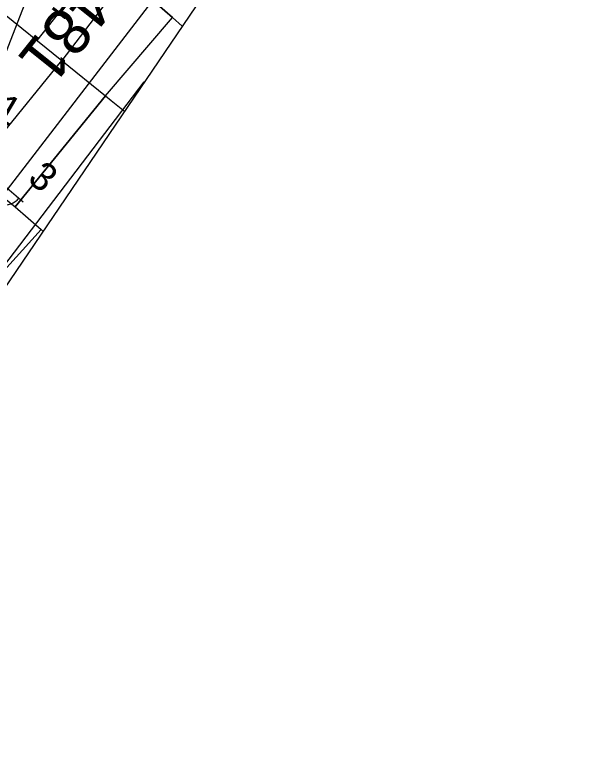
# Model space of a CAD drawing. Extents: x -621145 to -620110, y -1122807 to -1121971.
# Drawn here: x -620223.71 to -620192.94, y -1122754.28 to -1122715.36 of the extents above; entities that cross this region are included whole.
import ezdxf

# ---------------------------------------------------------------- set-up
doc = ezdxf.new("R2010")
doc.units = 0
for name, color, linetype in [('POPIS KABELOVÉ TRASY', 7, 'Continuous'), ('RÁMY', 7, 'Continuous'), ('SON-kanalizace', 7, 'Continuous'), ('Vrstva 25', 7, 'Continuous'), ('Vrstva 3', 7, 'Continuous'), ('Vrstva 53', 7, 'Continuous'), ('Vrstva 55', 7, 'Continuous'), ('Vrstva 56', 7, 'Continuous'), ('Vrstva 57', 7, 'Continuous'), ('Vrstva 6', 7, 'Continuous')]:
    doc.layers.add(name, color=color, linetype=linetype)

msp = doc.modelspace()

# ---------------------------------------------------------------- linework, layer by layer
at = {"layer": 'POPIS KABELOVÉ TRASY'}
msp.add_lwpolyline([(-620228.339, -1122728.069), (-620218.049, -1122701.604), (-620224.371, -1122697.311)], dxfattribs=at)
at = {"layer": 'RÁMY'}
for points in [[(-621061.558, -1122093.918), (-620192.937, -1122683.831), (-620276.367, -1122806.679), (-621144.989, -1122216.766)], [(-620887.834, -1122211.901), (-620192.937, -1122683.831), (-620276.367, -1122806.679), (-620971.264, -1122334.748)]]:
    msp.add_lwpolyline(points, close=True, dxfattribs=at)
at = {"layer": 'SON-kanalizace'}
msp.add_line((-620218.226, -1122711.312), (-620222.528, -1122716.741), dxfattribs=at)
msp.add_lwpolyline([(-620225.128, -1122704.565), (-620219.234, -1122709.235), (-620216.418, -1122711.556), (-620221.19, -1122717.82)], dxfattribs=at)
at = {"layer": 'Vrstva 25'}
msp.add_line((-620225.24, -1122723.667), (-620223.256, -1122725.347), dxfattribs=at)
msp.add_arc((-620224.256, -1122724.517), 1, 139.0457, 320.4509, dxfattribs=at)
at = {"layer": 'Vrstva 3'}
msp.add_line((-620230.199, -1122732.623), (-620210.91, -1122707.563), dxfattribs=at)
at = {"layer": 'Vrstva 53'}
for p, q in [((-620226.24, -1122705.93), (-620215.29, -1122715.52)), ((-620228.95, -1122711.56), (-620221.19, -1122717.82)), ((-620218.86, -1122719.7), (-620215.29, -1122715.52)), ((-620221.19, -1122717.82), (-620218.86, -1122719.7)), ((-620218.86, -1122719.7), (-620223.68, -1122725.62)), ((-620226.02, -1122723.74), (-620223.68, -1122725.62)), ((-620223.68, -1122725.62), (-620222.3, -1122726.83)), ((-620222.3, -1122726.83), (-620225.04, -1122729.85))]:
    msp.add_line(p, q, dxfattribs=at)
at = {"layer": 'Vrstva 55'}
for p, q in [((-620215.29, -1122715.52), (-620226.24, -1122705.93)), ((-620228.95, -1122711.56), (-620221.19, -1122717.82)), ((-620218.86, -1122719.7), (-620215.29, -1122715.52)), ((-620214.768, -1122715.977), (-620215.29, -1122715.52)), ((-620221.19, -1122717.82), (-620218.86, -1122719.7)), ((-620223.68, -1122725.62), (-620218.86, -1122719.7)), ((-620218.86, -1122719.7), (-620218.55, -1122719.95)), ((-620218.55, -1122719.95), (-620217.85, -1122720.514)), ((-620226.02, -1122723.74), (-620223.68, -1122725.62)), ((-620223.68, -1122725.62), (-620222.3, -1122726.83)), ((-620222.3, -1122726.83), (-620225.04, -1122729.85)), ((-620222.3, -1122726.83), (-620222.196, -1122726.913))]:
    msp.add_line(p, q, dxfattribs=at)
at = {"layer": 'Vrstva 56'}
msp.add_line((-620226.02, -1122723.74), (-620221.19, -1122717.82), dxfattribs=at)
at = {"layer": 'Vrstva 6'}
msp.add_line((-620226.831, -1122732.095), (-620216.793, -1122718.958), dxfattribs=at)

# ---------------------------------------------------------------- texts
at = {"layer": 'Vrstva 25'}
msp.add_text('3', height=1.5, rotation=319.7483, dxfattribs=at).set_placement((-620223.08, -1122724.208))
at = {"layer": 'Vrstva 3'}
msp.add_text('km 63,481', height=2.5, rotation=231.4071, dxfattribs=at).set_placement((-620213.881, -1122705.487))
at = {"layer": 'Vrstva 57'}
for s, rotation, p in [('3219/11', 322.1138, (-620226.689, -1122711.218)), ('2982/1', 329.4, (-620229.235, -1122718.229))]:
    msp.add_text(s, height=1.5, rotation=rotation, dxfattribs=at).set_placement(p)

doc.saveas('drawing.dxf')
